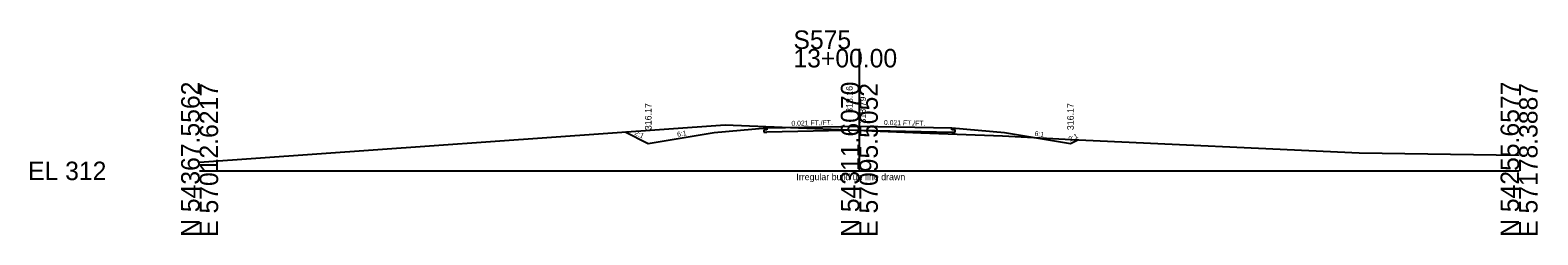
# Model space of a CAD drawing. Extents: x 10119 to 10347, y 94341 to 98867.
# Drawn here: x 10118.6 to 10347.2, y 96841.1 to 96872.1 of the extents above; entities that cross this region are included whole.
import ezdxf

# ---------------------------------------------------------------- set-up
doc = ezdxf.new("R2010")
doc.units = 0
for name, color, linetype in [('Level 10', 7, 'Continuous'), ('Level 11', 7, 'Continuous'), ('Level 12', 7, 'Continuous'), ('Level 32', 7, 'Continuous'), ('Level 33', 7, 'Continuous'), ('Level 50', 7, 'Continuous'), ('Level 59', 7, 'Continuous'), ('Level 6', 7, 'Continuous'), ('Level 60', 7, 'Continuous'), ('Level 63', 7, 'Continuous'), ('Level 7', 7, 'Continuous')]:
    doc.layers.add(name, color=color, linetype=linetype)

msp = doc.modelspace()

# ---------------------------------------------------------------- linework, layer by layer
at = {"layer": 'Level 11'}
for p, q in [((10230.31, 96857.31), (10230.31, 96857.02)), ((10258.31, 96857.02), (10258.31, 96857.31)), ((10230.31, 96857.02), (10229.81, 96857.01)), ((10229.81, 96857.01), (10229.81, 96856.67)), ((10229.81, 96856.67), (10230.31, 96856.68)), ((10258.81, 96857.01), (10258.31, 96857.02)), ((10258.31, 96856.68), (10258.81, 96856.67)), ((10258.81, 96856.67), (10258.81, 96857.01))]:
    msp.add_line(p, q, dxfattribs=at)
at = {"layer": 'Level 12'}
for q in [(10230.31, 96856.68), (10258.31, 96856.68)]:
    msp.add_line((10244.31, 96856.97), q, dxfattribs=at)
at = {"layer": 'Level 59'}
for p, q in [((10230.31, 96857.31), (10244.31, 96857.6)), ((10244.31, 96857.6), (10258.31, 96857.31))]:
    msp.add_line(p, q, dxfattribs=at)
at = {"layer": 'Level 6'}
for p, q in [((10222.31, 96856.64), (10230.31, 96857.31)), ((10258.31, 96857.31), (10266.31, 96856.64))]:
    msp.add_line(p, q, dxfattribs=at)
at = {"layer": 'Level 60'}
for p, q in [((10144.31, 96852.15), (10223.98, 96857.81)), ((10223.98, 96857.81), (10253.65, 96856.57)), ((10253.65, 96856.57), (10265.99, 96856.14)), ((10265.99, 96856.14), (10276.49, 96855.57)), ((10276.49, 96855.57), (10320.07, 96853.53)), ((10320.07, 96853.53), (10344.31, 96853.2))]:
    msp.add_line(p, q, dxfattribs=at)
at = {"layer": 'Level 63'}
for p, q in [((10244.31, 96850.81), (10244.31, 96869.29)), ((10144.31, 96850.81), (10244.31, 96850.81)), ((10244.31, 96850.81), (10344.31, 96850.81))]:
    msp.add_line(p, q, dxfattribs=at)
at = {"layer": 'Level 7'}
for p, q in [((10208.8, 96856.73), (10212.31, 96854.98)), ((10212.31, 96854.98), (10222.31, 96856.64)), ((10266.31, 96856.64), (10276.31, 96854.98)), ((10276.31, 96854.98), (10277.42, 96855.53))]:
    msp.add_line(p, q, dxfattribs=at)

# ---------------------------------------------------------------- texts
at = {"layer": 'Level 10'}
msp.add_text('318.16', height=1, rotation=90, dxfattribs=at).set_placement((10243.31, 96859.59))
at = {"layer": 'Level 32'}
for s, rotation, p in [('0.021 FT./FT.', 1.1916, (10234.02, 96857.64)), ('0.021 FT./FT.', 358.8084, (10248.03, 96857.77)), ('2:1', 333.435, (10210.16, 96856.33)), ('6:1', 9.4623, (10216.75, 96855.97)), ('6:1', 350.5377, (10270.83, 96856.14)), ('2:1', 26.5651, (10276.25, 96855.22))]:
    msp.add_text(s, height=0.75, rotation=rotation, dxfattribs=at).set_placement(p)
at = {"layer": 'Level 33'}
for p in [(10212.81, 96856.98), (10276.81, 96856.98)]:
    msp.add_text('316.17', height=1, rotation=90, dxfattribs=at).set_placement(p)
at = {"layer": 'Level 50'}
msp.add_text('Irregular build up line drawn', height=1, dxfattribs=at).set_placement((10234.76, 96849.4))
at = {"layer": 'Level 59'}
msp.add_text(' 318.79', height=1, rotation=90, dxfattribs=at).set_placement((10245.31, 96857.6))
at = {"layer": 'Level 63'}
for s, p in [('S575', (10234.32, 96869.29)), ('13+00.00', (10234.32, 96866.49)), ('EL 312', (10118.31, 96849.41))]:
    msp.add_text(s, height=2.8, dxfattribs=at).set_placement(p)
for s, p in [('N 54367.5562', (10144.31, 96840.81)), ('E 57012.6217', (10147.11, 96840.81)), ('N 54311.6070', (10244.31, 96840.81)), ('E 57095.5052', (10247.11, 96840.81)), ('N 54255.6577', (10344.31, 96840.81)), ('E 57178.3887', (10347.11, 96840.81))]:
    msp.add_text(s, height=2.8, rotation=90, dxfattribs=at).set_placement(p)

doc.saveas('drawing.dxf')
